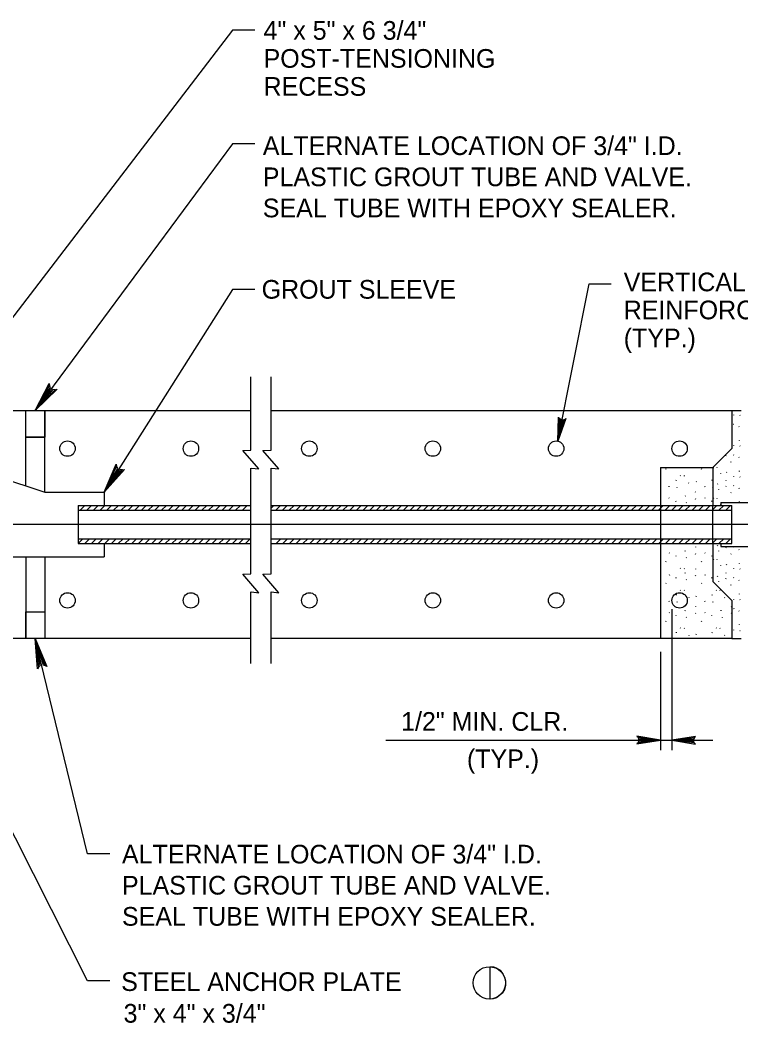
# Model space of a CAD drawing. Extents: x 641328 to 643024, y 298283 to 300065.
# Drawn here: x 642325.5 to 642441.2, y 299080.1 to 299241.2 of the extents above; entities that cross this region are included whole.
import ezdxf

# ---------------------------------------------------------------- set-up
doc = ezdxf.new("R2010")
doc.units = 0
for name, color, linetype in [('1', 7, 'Continuous'), ('2', 7, 'Continuous'), ('Default', 7, 'Continuous')]:
    doc.layers.add(name, color=color, linetype=linetype)

msp = doc.modelspace()

# ---------------------------------------------------------------- linework, layer by layer
at = {"layer": '1'}
msp.add_lwpolyline([(642400.95, 299089.16), (642401.49, 299089.11), (642401.92, 299088.97), (642402.55, 299088.58), (642402.95, 299088.08), (642403.25, 299087.48), (642403.43, 299086.91), (642403.41, 299086.17), (642403.23, 299085.51), (642402.87, 299084.92), (642402.44, 299084.51), (642401.96, 299084.17), (642401.42, 299084), (642400.95, 299083.96)], close=True, dxfattribs=at)
msp.add_circle((642400.82, 299086.56), 2.6, dxfattribs=at)
at = {"layer": '2'}
for p, q in [((642359.57, 299239.6), (642303.45, 299166.28)), ((642359.57, 299221.33), (642327.91, 299178.47)), ((642411.79, 299173.58), (642416.87, 299198.86)), ((642416.87, 299198.86), (642420.36, 299198.86)), ((642359.57, 299197.95), (642338.98, 299165.36)), ((642362.55, 299172.12), (642362.55, 299183.88)), ((642365.78, 299172.12), (642365.78, 299183.88)), ((642289.8, 299178.47), (642329.43, 299165.36)), ((642326.39, 299166.37), (642326.39, 299178.47)), ((642329.43, 299165.36), (642329.43, 299178.47)), ((642411.79, 299173.58), (642411.92, 299177.43)), ((642411.92, 299177.43), (642412.05, 299177.2)), ((642439.74, 299178.47), (642441.27, 299178.47)), ((642439.99, 299177.82), (642440.02, 299177.76)), ((642441.02, 299177.72), (642441.06, 299177.67)), ((642412.05, 299177.2), (642411.79, 299173.58)), ((642413.12, 299177.19), (642411.79, 299173.58)), ((642411.79, 299173.58), (642412.92, 299177.04)), ((642411.79, 299173.58), (642412.28, 299177.02)), ((642411.79, 299173.58), (642412.46, 299176.99)), ((642412.64, 299176.96), (642411.79, 299173.58)), ((642412.28, 299177.02), (642412.05, 299177.2)), ((642412.64, 299176.96), (642412.28, 299177.02)), ((642412.92, 299177.04), (642412.64, 299176.96)), ((642412.92, 299177.04), (642413.12, 299177.19)), ((642440.02, 299176.32), (642440.05, 299176.27)), ((642440.89, 299175.93), (642440.9, 299175.85)), ((642326.39, 299174.22), (642329.43, 299174.22)), ((642439.99, 299172.88), (642440.02, 299172.83)), ((642440.97, 299173.65), (642441, 299173.72)), ((642441.02, 299172.79), (642441.06, 299172.74)), ((642438.8, 299171.22), (642438.84, 299171.3)), ((642440.02, 299171.39), (642440.05, 299171.33)), ((642440.89, 299171), (642440.9, 299170.92)), ((642436.82, 299169.36), (642436.86, 299169.31)), ((642437.32, 299169.34), (642437.36, 299169.29)), ((642439.6, 299170.2), (642439.64, 299170.28)), ((642362.55, 299152.25), (642362.55, 299169.23)), ((642365.78, 299152.25), (642365.78, 299169.23)), ((642428.31, 299169.32), (642436.69, 299169.32)), ((642428.31, 299169.32), (642428.31, 299163.23)), ((642429.15, 299169.08), (642429.19, 299169.18)), ((642431.47, 299168.05), (642431.51, 299167.99)), ((642432.08, 299168.03), (642432.12, 299167.96)), ((642434.89, 299169.08), (642434.93, 299169.18)), ((642436.72, 299169.21), (642436.74, 299169.19)), ((642437.91, 299168.41), (642437.94, 299168.35)), ((642438.89, 299168.51), (642438.92, 299168.59)), ((642439.99, 299167.95), (642440.02, 299167.9)), ((642440.97, 299168.71), (642441, 299168.79)), ((642441.02, 299167.85), (642441.06, 299167.8)), ((642428.31, 299167.1), (642428.32, 299167.1)), ((642429.62, 299166.32), (642429.66, 299166.25)), ((642430.83, 299167.25), (642430.87, 299167.35)), ((642430.9, 299166.2), (642430.94, 299166.13)), ((642432.8, 299166.88), (642432.85, 299166.82)), ((642434.01, 299167.01), (642434.06, 299167.1)), ((642435.36, 299166.32), (642435.4, 299166.25)), ((642436.57, 299167.25), (642436.61, 299167.35)), ((642436.64, 299166.2), (642436.68, 299166.13)), ((642436.72, 299166.75), (642436.74, 299166.72)), ((642437.47, 299166.64), (642437.5, 299166.72)), ((642438.77, 299167.23), (642438.81, 299167.18)), ((642438.8, 299166.28), (642438.84, 299166.36)), ((642440.02, 299166.45), (642440.05, 299166.4)), ((642329.43, 299165.36), (642338.98, 299165.36)), ((642338.98, 299165.36), (642338.98, 299163.23)), ((642432.26, 299164.71), (642432.31, 299164.81)), ((642433.87, 299165.43), (642433.91, 299165.37)), ((642437.6, 299165.83), (642437.63, 299165.78)), ((642439.6, 299165.26), (642439.64, 299165.34)), ((642440.89, 299166.06), (642440.9, 299165.98)), ((642334.78, 299163.23), (642346.71, 299163.23)), ((642334.78, 299163.23), (642334.78, 299157.13)), ((642335.11, 299162.47), (642335.87, 299163.23)), ((642336.19, 299162.47), (642336.95, 299163.23)), ((642337.26, 299162.47), (642338.03, 299163.23)), ((642338.34, 299162.47), (642339.1, 299163.23)), ((642339.42, 299162.47), (642340.18, 299163.23)), ((642340.5, 299162.47), (642341.26, 299163.23)), ((642341.73, 299162.47), (642342.5, 299163.23)), ((642342.81, 299162.47), (642343.57, 299163.23)), ((642343.9, 299162.47), (642344.66, 299163.23)), ((642344.98, 299162.47), (642345.74, 299163.23)), ((642346.05, 299162.47), (642346.82, 299163.23)), ((642346.71, 299163.23), (642362.55, 299163.23)), ((642347.13, 299162.47), (642347.89, 299163.23)), ((642348.21, 299162.47), (642348.97, 299163.23)), ((642349.29, 299162.47), (642350.05, 299163.23)), ((642350.36, 299162.47), (642351.13, 299163.23)), ((642351.44, 299162.47), (642352.2, 299163.23)), ((642352.52, 299162.47), (642353.28, 299163.23)), ((642353.6, 299162.47), (642354.36, 299163.23)), ((642354.68, 299162.47), (642355.44, 299163.23)), ((642355.75, 299162.47), (642356.52, 299163.23)), ((642356.83, 299162.47), (642357.59, 299163.23)), ((642357.91, 299162.47), (642358.67, 299163.23)), ((642358.99, 299162.47), (642359.76, 299163.23)), ((642360.08, 299162.47), (642360.85, 299163.23)), ((642361.17, 299162.47), (642361.93, 299163.23)), ((642365.78, 299163.23), (642439.74, 299163.23)), ((642365.78, 299162.78), (642366.23, 299163.23)), ((642366.54, 299162.47), (642367.31, 299163.23)), ((642367.62, 299162.47), (642368.38, 299163.23)), ((642368.7, 299162.47), (642369.46, 299163.23)), ((642369.78, 299162.47), (642370.54, 299163.23)), ((642370.85, 299162.47), (642371.62, 299163.23)), ((642371.93, 299162.47), (642372.69, 299163.23)), ((642373.01, 299162.47), (642373.77, 299163.23)), ((642374.09, 299162.47), (642374.85, 299163.23)), ((642375.17, 299162.47), (642375.93, 299163.23)), ((642376.24, 299162.47), (642377.01, 299163.23)), ((642377.32, 299162.47), (642378.08, 299163.23)), ((642378.4, 299162.47), (642379.16, 299163.23)), ((642379.48, 299162.47), (642380.24, 299163.23)), ((642380.55, 299162.47), (642381.32, 299163.23)), ((642381.63, 299162.47), (642382.39, 299163.23)), ((642382.71, 299162.47), (642383.47, 299163.23)), ((642383.79, 299162.47), (642384.55, 299163.23)), ((642384.86, 299162.47), (642385.63, 299163.23)), ((642385.94, 299162.47), (642386.7, 299163.23)), ((642387.02, 299162.47), (642387.78, 299163.23)), ((642388.1, 299162.47), (642388.86, 299163.23)), ((642389.17, 299162.47), (642389.94, 299163.23)), ((642390.25, 299162.47), (642391.01, 299163.23)), ((642391.33, 299162.47), (642392.09, 299163.23)), ((642392.41, 299162.47), (642393.17, 299163.23)), ((642393.49, 299162.47), (642394.25, 299163.23)), ((642394.56, 299162.47), (642395.32, 299163.23)), ((642395.64, 299162.47), (642396.4, 299163.23)), ((642396.72, 299162.47), (642397.48, 299163.23)), ((642397.8, 299162.47), (642398.56, 299163.23)), ((642398.87, 299162.47), (642399.64, 299163.23)), ((642399.95, 299162.47), (642400.71, 299163.23)), ((642401.03, 299162.47), (642401.79, 299163.23)), ((642402.11, 299162.47), (642402.87, 299163.23)), ((642403.18, 299162.47), (642403.95, 299163.23)), ((642404.26, 299162.47), (642405.02, 299163.23)), ((642405.34, 299162.47), (642406.1, 299163.23)), ((642406.42, 299162.47), (642407.18, 299163.23)), ((642407.49, 299162.47), (642408.26, 299163.23)), ((642408.57, 299162.47), (642409.33, 299163.23)), ((642409.65, 299162.47), (642410.41, 299163.23)), ((642410.73, 299162.47), (642411.49, 299163.23)), ((642411.81, 299162.47), (642412.57, 299163.23)), ((642412.88, 299162.47), (642413.64, 299163.23)), ((642413.96, 299162.47), (642414.72, 299163.23)), ((642415.04, 299162.47), (642415.8, 299163.23)), ((642416.12, 299162.47), (642416.88, 299163.23)), ((642417.19, 299162.47), (642417.96, 299163.23)), ((642418.27, 299162.47), (642419.03, 299163.23)), ((642419.35, 299162.47), (642420.11, 299163.23)), ((642420.43, 299162.47), (642421.19, 299163.23)), ((642421.5, 299162.47), (642422.27, 299163.23)), ((642422.58, 299162.47), (642423.34, 299163.23)), ((642423.66, 299162.47), (642424.42, 299163.23)), ((642424.74, 299162.47), (642425.5, 299163.23)), ((642425.81, 299162.47), (642426.58, 299163.23)), ((642426.89, 299162.47), (642427.65, 299163.23)), ((642427.97, 299162.47), (642428.73, 299163.23)), ((642428.31, 299163.23), (642428.31, 299157.13)), ((642429.05, 299162.47), (642429.81, 299163.23)), ((642429.66, 299164.47), (642429.7, 299164.41)), ((642430.12, 299162.47), (642430.89, 299163.23)), ((642430.73, 299163.99), (642430.74, 299163.9)), ((642431.2, 299162.47), (642431.96, 299163.23)), ((642432.28, 299162.47), (642433.04, 299163.23)), ((642432.42, 299163.71), (642432.46, 299163.64)), ((642433.36, 299162.47), (642434.12, 299163.23)), ((642433.9, 299164.27), (642433.95, 299164.36)), ((642434.43, 299162.47), (642435.2, 299163.23)), ((642435.4, 299164.47), (642435.44, 299164.41)), ((642435.51, 299162.47), (642436.27, 299163.23)), ((642436.47, 299163.99), (642436.48, 299163.9)), ((642436.6, 299162.47), (642437.36, 299163.23)), ((642436.69, 299157.13), (642436.69, 299163.23)), ((642436.72, 299164.28), (642436.74, 299164.25)), ((642436.82, 299164.43), (642436.86, 299164.37)), ((642437.32, 299164.41), (642437.36, 299164.35)), ((642437.68, 299162.47), (642438.44, 299163.23)), ((642437.91, 299163.47), (642437.94, 299163.42)), ((642438, 299163.69), (642443.01, 299163.69)), ((642438, 299163.69), (642438, 299163.23)), ((642438.77, 299162.47), (642439.53, 299163.23)), ((642439.74, 299157.13), (642439.74, 299163.23)), ((642440.97, 299163.78), (642441, 299163.86)), ((642334.78, 299162.47), (642362.55, 299162.47)), ((642365.78, 299162.47), (642439.74, 299162.47)), ((642522.43, 299160.18), (642228.66, 299160.18)), ((642334.78, 299157.13), (642335.54, 299157.89)), ((642334.78, 299157.89), (642362.55, 299157.89)), ((642334.78, 299157.13), (642362.55, 299157.13)), ((642335.86, 299157.13), (642336.62, 299157.89)), ((642336.94, 299157.13), (642337.7, 299157.89)), ((642338.01, 299157.13), (642338.78, 299157.89)), ((642338.98, 299157.13), (642338.98, 299155)), ((642339.09, 299157.13), (642339.85, 299157.89)), ((642340.17, 299157.13), (642340.93, 299157.89)), ((642341.25, 299157.13), (642342.01, 299157.89)), ((642342.32, 299157.13), (642343.09, 299157.89)), ((642343.4, 299157.13), (642344.16, 299157.89)), ((642344.48, 299157.13), (642345.24, 299157.89)), ((642345.56, 299157.13), (642346.32, 299157.89)), ((642346.63, 299157.13), (642347.4, 299157.89)), ((642347.71, 299157.13), (642348.47, 299157.89)), ((642348.79, 299157.13), (642349.55, 299157.89)), ((642349.87, 299157.13), (642350.63, 299157.89)), ((642350.94, 299157.13), (642351.71, 299157.89)), ((642352.02, 299157.13), (642352.78, 299157.89)), ((642353.1, 299157.13), (642353.86, 299157.89)), ((642354.18, 299157.13), (642354.94, 299157.89)), ((642355.26, 299157.13), (642356.02, 299157.89)), ((642356.33, 299157.13), (642357.09, 299157.89)), ((642357.41, 299157.13), (642358.17, 299157.89)), ((642358.49, 299157.13), (642359.25, 299157.89)), ((642359.57, 299157.13), (642360.33, 299157.89)), ((642360.6, 299157.13), (642361.36, 299157.89)), ((642361.69, 299157.13), (642362.55, 299157.99)), ((642365.78, 299157.89), (642439.74, 299157.89)), ((642365.78, 299157.13), (642439.74, 299157.13)), ((642366.57, 299157.13), (642367.33, 299157.89)), ((642367.67, 299157.13), (642368.43, 299157.89)), ((642368.74, 299157.13), (642369.51, 299157.89)), ((642369.82, 299157.13), (642370.58, 299157.89)), ((642370.9, 299157.13), (642371.66, 299157.89)), ((642371.98, 299157.13), (642372.74, 299157.89)), ((642373.05, 299157.13), (642373.82, 299157.89)), ((642374.13, 299157.13), (642374.89, 299157.89)), ((642375.21, 299157.13), (642375.97, 299157.89)), ((642376.29, 299157.13), (642377.05, 299157.89)), ((642377.36, 299157.13), (642378.13, 299157.89)), ((642378.44, 299157.13), (642379.2, 299157.89)), ((642379.52, 299157.13), (642380.28, 299157.89)), ((642380.6, 299157.13), (642381.36, 299157.89)), ((642381.68, 299157.13), (642382.44, 299157.89)), ((642382.75, 299157.13), (642383.52, 299157.89)), ((642383.83, 299157.13), (642384.59, 299157.89)), ((642384.91, 299157.13), (642385.67, 299157.89)), ((642385.99, 299157.13), (642386.75, 299157.89)), ((642387.06, 299157.13), (642387.83, 299157.89)), ((642388.14, 299157.13), (642388.9, 299157.89)), ((642389.22, 299157.13), (642389.98, 299157.89)), ((642390.3, 299157.13), (642391.06, 299157.89)), ((642391.37, 299157.13), (642392.14, 299157.89)), ((642392.45, 299157.13), (642393.21, 299157.89)), ((642393.53, 299157.13), (642394.29, 299157.89)), ((642394.61, 299157.13), (642395.37, 299157.89)), ((642395.68, 299157.13), (642396.45, 299157.89)), ((642396.76, 299157.13), (642397.52, 299157.89)), ((642397.84, 299157.13), (642398.6, 299157.89)), ((642398.92, 299157.13), (642399.68, 299157.89)), ((642400, 299157.13), (642400.76, 299157.89)), ((642401.07, 299157.13), (642401.83, 299157.89)), ((642402.15, 299157.13), (642402.91, 299157.89)), ((642403.23, 299157.13), (642403.99, 299157.89)), ((642404.31, 299157.13), (642405.07, 299157.89)), ((642405.38, 299157.13), (642406.15, 299157.89)), ((642406.46, 299157.13), (642407.22, 299157.89)), ((642407.54, 299157.13), (642408.3, 299157.89)), ((642408.62, 299157.13), (642409.38, 299157.89)), ((642409.69, 299157.13), (642410.46, 299157.89)), ((642410.77, 299157.13), (642411.53, 299157.89)), ((642411.85, 299157.13), (642412.61, 299157.89)), ((642412.93, 299157.13), (642413.69, 299157.89)), ((642414, 299157.13), (642414.77, 299157.89)), ((642415.08, 299157.13), (642415.84, 299157.89)), ((642416.16, 299157.13), (642416.92, 299157.89)), ((642417.24, 299157.13), (642418, 299157.89)), ((642418.32, 299157.13), (642419.08, 299157.89)), ((642419.39, 299157.13), (642420.15, 299157.89)), ((642420.47, 299157.13), (642421.23, 299157.89)), ((642421.55, 299157.13), (642422.31, 299157.89)), ((642422.63, 299157.13), (642423.39, 299157.89)), ((642423.7, 299157.13), (642424.47, 299157.89)), ((642424.78, 299157.13), (642425.54, 299157.89)), ((642425.86, 299157.13), (642426.62, 299157.89)), ((642426.94, 299157.13), (642427.7, 299157.89)), ((642428.01, 299157.13), (642428.78, 299157.89)), ((642428.31, 299157.13), (642428.31, 299141.89)), ((642429.09, 299157.13), (642429.85, 299157.89)), ((642430.17, 299157.13), (642430.93, 299157.89)), ((642431.25, 299157.13), (642432.01, 299157.89)), ((642432.28, 299157.13), (642433.04, 299157.89)), ((642433.36, 299157.13), (642434.12, 299157.89)), ((642433.89, 299156.61), (642433.93, 299156.55)), ((642434.43, 299157.13), (642435.2, 299157.89)), ((642435.51, 299157.13), (642436.27, 299157.89)), ((642436.6, 299157.13), (642437.36, 299157.89)), ((642436.72, 299156.88), (642436.74, 299156.85)), ((642437.47, 299156.77), (642437.5, 299156.85)), ((642437.68, 299157.13), (642438.44, 299157.89)), ((642438, 299157.13), (642438, 299156.67)), ((642438, 299156.67), (642443.01, 299156.67)), ((642438.77, 299157.13), (642439.53, 299157.89)), ((642438.8, 299156.41), (642438.84, 299156.49)), ((642440.02, 299156.58), (642440.05, 299156.53)), ((642336.29, 299086.88), (642301.89, 299155.07)), ((642318.94, 299155), (642338.98, 299155)), ((642326.39, 299155), (642326.39, 299141.89)), ((642329.43, 299155), (642329.43, 299141.89)), ((642429.68, 299155.65), (642429.72, 299155.59)), ((642430.75, 299155.17), (642430.76, 299155.08)), ((642432.28, 299155.89), (642432.32, 299155.98)), ((642432.44, 299154.89), (642432.48, 299154.82)), ((642433.92, 299155.44), (642433.96, 299155.54)), ((642435.42, 299155.65), (642435.46, 299155.59)), ((642436.49, 299155.17), (642436.5, 299155.08)), ((642437.6, 299155.96), (642437.63, 299155.91)), ((642439.6, 299155.4), (642439.64, 299155.48)), ((642440.89, 299156.19), (642440.9, 299156.11)), ((642429.16, 299154.19), (642429.21, 299154.29)), ((642434.9, 299154.19), (642434.95, 299154.29)), ((642436.72, 299154.41), (642436.74, 299154.38)), ((642436.82, 299154.56), (642436.86, 299154.51)), ((642437.32, 299154.54), (642437.36, 299154.49)), ((642437.91, 299153.6), (642437.94, 299153.55)), ((642438.89, 299153.71), (642438.92, 299153.79)), ((642440.97, 299153.91), (642441, 299153.99)), ((642429.68, 299152.14), (642429.72, 299152.07)), ((642430.75, 299151.66), (642430.76, 299151.56)), ((642431.48, 299153.16), (642431.53, 299153.1)), ((642432.1, 299153.14), (642432.14, 299153.07)), ((642432.28, 299152.37), (642432.32, 299152.47)), ((642433.9, 299153.07), (642433.93, 299153.03)), ((642433.92, 299151.93), (642433.96, 299152.03)), ((642435.42, 299152.14), (642435.46, 299152.07)), ((642436.49, 299151.66), (642436.5, 299151.56)), ((642436.72, 299151.94), (642436.74, 299151.92)), ((642437.47, 299151.84), (642437.5, 299151.92)), ((642438.77, 299152.43), (642438.81, 299152.38)), ((642439.99, 299153.15), (642440.02, 299153.09)), ((642440.02, 299151.65), (642440.05, 299151.6)), ((642441.02, 299153.05), (642441.06, 299153)), ((642429.16, 299150.68), (642429.21, 299150.78)), ((642432.44, 299151.37), (642432.48, 299151.31)), ((642434.9, 299150.68), (642434.95, 299150.78)), ((642437.6, 299151.03), (642437.63, 299150.97)), ((642438.8, 299151.48), (642438.84, 299151.56)), ((642439.6, 299150.46), (642439.64, 299150.54)), ((642440.89, 299151.26), (642440.9, 299151.18)), ((642362.55, 299137.88), (642362.55, 299149.36)), ((642365.78, 299137.88), (642365.78, 299149.36)), ((642428.31, 299148.65), (642428.33, 299148.7)), ((642430.85, 299148.85), (642430.89, 299148.94)), ((642431.48, 299149.65), (642431.53, 299149.58)), ((642432.1, 299149.62), (642432.14, 299149.56)), ((642432.82, 299148.47), (642432.86, 299148.41)), ((642434.03, 299148.6), (642434.07, 299148.7)), ((642436.59, 299148.85), (642436.63, 299148.94)), ((642437.22, 299149.65), (642437.27, 299149.58)), ((642437.84, 299149.62), (642437.88, 299149.56)), ((642438.56, 299148.47), (642438.6, 299148.41)), ((642438.91, 299148.82), (642438.92, 299148.85)), ((642440.97, 299148.97), (642441, 299149.05)), ((642429.64, 299147.91), (642429.68, 299147.84)), ((642430.91, 299147.79), (642430.96, 299147.73)), ((642433.89, 299147.03), (642433.93, 299146.96)), ((642435.38, 299147.91), (642435.42, 299147.84)), ((642436.65, 299147.79), (642436.7, 299147.73)), ((642439.62, 299147.03), (642439.67, 299146.96)), ((642439.99, 299148.21), (642440.02, 299148.16)), ((642441.02, 299148.12), (642441.06, 299148.06)), ((642429.68, 299146.07), (642429.72, 299146)), ((642430.12, 299146.6), (642430.12, 299123.92)), ((642430.75, 299145.59), (642430.76, 299145.49)), ((642432.28, 299146.3), (642432.32, 299146.4)), ((642432.44, 299145.3), (642432.48, 299145.24)), ((642433.92, 299145.86), (642433.96, 299145.96)), ((642435.42, 299146.07), (642435.46, 299146)), ((642436.49, 299145.59), (642436.5, 299145.49)), ((642438.02, 299146.3), (642438.06, 299146.4)), ((642438.18, 299145.3), (642438.22, 299145.24)), ((642439.66, 299145.86), (642439.7, 299145.96)), ((642440.02, 299146.72), (642440.05, 299146.66)), ((642440.89, 299146.32), (642440.9, 299146.25)), ((642429.16, 299144.61), (642429.21, 299144.7)), ((642431.48, 299143.58), (642431.53, 299143.51)), ((642434.9, 299144.61), (642434.95, 299144.7)), ((642437.22, 299143.58), (642437.27, 299143.51)), ((642440.97, 299144.04), (642441, 299144.12)), ((642428.31, 299142.58), (642428.33, 299142.63)), ((642430.85, 299142.78), (642430.89, 299142.87)), ((642432.1, 299143.55), (642432.14, 299143.49)), ((642432.82, 299142.4), (642432.86, 299142.34)), ((642434.03, 299142.53), (642434.07, 299142.63)), ((642436.59, 299142.78), (642436.63, 299142.87)), ((642437.84, 299143.55), (642437.88, 299143.49)), ((642438.56, 299142.4), (642438.6, 299142.34)), ((642439.99, 299143.28), (642440.02, 299143.22)), ((642441.02, 299143.18), (642441.06, 299143.13)), ((642336.29, 299107.28), (642327.91, 299141.89)), ((642439.74, 299141.89), (642441.27, 299141.89)), ((642428.31, 299139.75), (642428.31, 299123.92)), ((642428.31, 299125.55), (642424.52, 299126.18)), ((642424.52, 299126.18), (642424.71, 299126.01)), ((642424.84, 299125.75), (642424.71, 299126.01)), ((642424.71, 299126.01), (642428.31, 299125.55)), ((642433.93, 299126.14), (642430.12, 299125.55)), ((642430.12, 299125.55), (642433.73, 299125.98)), ((642433.73, 299125.98), (642433.6, 299125.71)), ((642433.73, 299125.98), (642433.93, 299126.14)), ((642384.2, 299125.55), (642436.71, 299125.55)), ((642424.51, 299124.96), (642428.31, 299125.55)), ((642424.7, 299125.12), (642424.51, 299124.96)), ((642428.31, 299125.55), (642424.7, 299125.12)), ((642424.7, 299125.12), (642424.84, 299125.38)), ((642428.31, 299125.55), (642424.84, 299125.75)), ((642424.84, 299125.38), (642424.84, 299125.75)), ((642428.31, 299125.55), (642424.84, 299125.56)), ((642424.84, 299125.38), (642428.31, 299125.55)), ((642433.6, 299125.71), (642430.12, 299125.55)), ((642430.12, 299125.55), (642433.6, 299125.35)), ((642433.72, 299125.09), (642430.12, 299125.55)), ((642430.12, 299125.55), (642433.92, 299124.91)), ((642430.12, 299125.55), (642433.6, 299125.53)), ((642433.6, 299125.71), (642433.6, 299125.35)), ((642433.6, 299125.35), (642433.72, 299125.09)), ((642433.92, 299124.91), (642433.72, 299125.09))]:
    msp.add_line(p, q, dxfattribs=at)
for points in [[(642331.12, 299181.83), (642330.75, 299181.89), (642327.91, 299178.47), (642331.12, 299181.83), (642331.42, 299181.9), (642327.91, 299178.47), (642330.37, 299182.17), (642330.2, 299182.49), (642327.91, 299178.47), (642330.17, 299182.83), (642330.2, 299182.49)], [(642289.66, 299178.47), (642362.55, 299178.47)], [(642365.83, 299178.47), (642439.74, 299178.47)], [(642439.74, 299178.47), (642439.74, 299172.37), (642436.69, 299169.32), (642436.69, 299163.23)], [(642362.62, 299169.22), (642363.79, 299169.11), (642361.24, 299172.08), (642362.55, 299172.12)], [(642365.86, 299169.22), (642367.02, 299169.11), (642364.47, 299172.08), (642365.78, 299172.12)], [(642341.94, 299168.95), (642341.56, 299168.98), (642338.98, 299165.36), (642341.94, 299168.95), (642342.23, 299169.04), (642338.98, 299165.36), (642341.17, 299169.23), (642340.97, 299169.54), (642338.98, 299165.36), (642340.92, 299169.87), (642340.97, 299169.54)], [(642436.69, 299157.13), (642436.69, 299151.04), (642439.74, 299147.99), (642439.74, 299141.89)], [(642362.62, 299149.35), (642363.79, 299149.23), (642361.24, 299152.2), (642362.55, 299152.25)], [(642365.86, 299149.35), (642367.02, 299149.23), (642364.47, 299152.2), (642365.78, 299152.25)], [(642362.55, 299141.89), (642289.66, 299141.89)], [(642328.43, 299137.27), (642328.72, 299137.52), (642327.91, 299141.89), (642328.43, 299137.27), (642328.29, 299136.99), (642327.91, 299141.89), (642329.17, 299137.63), (642329.53, 299137.55), (642327.91, 299141.89), (642329.8, 299137.36), (642329.53, 299137.55)], [(642439.74, 299141.89), (642365.83, 299141.89)]]:
    msp.add_lwpolyline(points, dxfattribs=at)
for points in [[(642326.39, 299178.47), (642329.43, 299178.47), (642329.43, 299174.22), (642326.39, 299174.22)], [(642326.39, 299146.14), (642329.43, 299146.14), (642329.43, 299141.89), (642326.39, 299141.89)]]:
    msp.add_lwpolyline(points, close=True, dxfattribs=at)
for centre in [(642333.1, 299172.37), (642352.91, 299172.37), (642371.92, 299172.37), (642391.74, 299172.37), (642411.55, 299172.37), (642431.36, 299172.37), (642333.1, 299147.99), (642352.91, 299147.99), (642371.92, 299147.99), (642391.74, 299147.99), (642411.55, 299147.99), (642431.36, 299147.99)]:
    msp.add_circle(centre, 1.24, dxfattribs=at)
at = {"layer": 'Default'}
for p, q in [((642363.18, 299239.6), (642359.57, 299239.6)), ((642363.18, 299221.33), (642359.57, 299221.33)), ((642363.18, 299197.95), (642359.57, 299197.95)), ((642339.89, 299107.28), (642336.29, 299107.28)), ((642339.89, 299086.88), (642336.29, 299086.88))]:
    msp.add_line(p, q, dxfattribs=at)

# ---------------------------------------------------------------- texts
at = {"layer": '2'}
for s, p in [('4" x 5" x 6 3/4"', (642364.57, 299238.04)), ('POST-TENSIONING', (642364.57, 299233.54)), ('RECESS', (642364.57, 299229.04)), ('ALTERNATE LOCATION OF 3/4" I.D.', (642364.45, 299219.52)), ('PLASTIC GROUT TUBE AND VALVE. ', (642364.45, 299214.52)), ('SEAL TUBE WITH EPOXY SEALER.', (642364.45, 299209.52)), ('VERTICAL', (642422.39, 299197.64)), ('GROUT SLEEVE', (642364.26, 299196.45)), ('REINFORCEMENT', (642422.39, 299193.14)), ('(TYP.)', (642422.39, 299188.64)), ('1/2" MIN. CLR.', (642386.65, 299127.05)), ('(TYP.)', (642397.22, 299121.05)), ('ALTERNATE LOCATION OF 3/4" I.D.', (642341.84, 299105.74)), ('PLASTIC GROUT TUBE AND VALVE.', (642341.84, 299100.74)), ('SEAL TUBE WITH EPOXY SEALER.', (642341.84, 299095.74)), ('STEEL ANCHOR PLATE', (642341.71, 299085.26)), ('3" x 4" x 3/4"', (642342.1, 299080.17))]:
    msp.add_text(s, height=3, dxfattribs=at).set_placement(p)

doc.saveas('drawing.dxf')
